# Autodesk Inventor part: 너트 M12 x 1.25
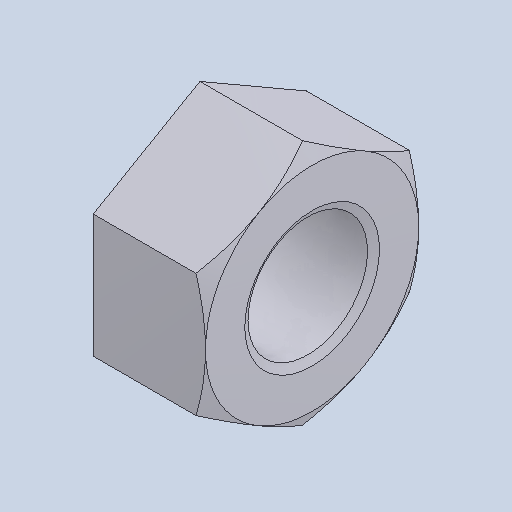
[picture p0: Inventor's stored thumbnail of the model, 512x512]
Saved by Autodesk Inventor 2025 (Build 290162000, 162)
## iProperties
Created: 2024-08
Part Number: 너트 M12 x 1.25
Material: 스테인리스강
Description: 6각 너트
Document SubType Name: Modeling
Designer: 학생
Density: 8.08 g/cm^3
Appearance: 기본값
Author: jhkim
Sending System: Autodesk Inventor 2025
Preprocessor: ST-DEVELOPER v20
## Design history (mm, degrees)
feature "Solid1"
node "솔리드1"
